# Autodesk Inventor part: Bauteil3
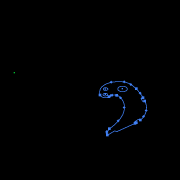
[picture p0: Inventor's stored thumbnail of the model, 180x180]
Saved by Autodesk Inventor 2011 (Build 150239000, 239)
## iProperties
Created: 2011-10
Part Number: Bauteil3
Document SubType Name: Modeling
Designer: em
Density: 1 g/cm^3
Author: em
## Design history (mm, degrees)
sketch "Skizze1"
  geometry: L1 (120.71, 20.889)-(122.705, 21.035); L2 (120.71, 20.889)-(120.347, 25.876); L3 (120.347, 25.876)-(120.71, 20.889); L4 (120.347, 25.876)-(122.342, 26.021); L5 (122.342, 26.021)-(120.347, 25.876); L6 (122.705, 21.035)-(120.71, 20.889); L7 (100.344, 48.759)-(101.309, 50.511); L8 (101.309, 50.511)-(100.344, 48.759); L9 (104.724, 46.348)-(100.344, 48.759); L10 (100.344, 48.759)-(104.724, 46.348); L11 (105.689, 48.1)-(104.724, 46.348); L12 (104.724, 46.348)-(105.689, 48.1); L13 (122.6, 19.531)-(120.219, 0); L14 (122.6, 19.531)-(120.219, 0); L15 (120.219, 0)-(118.272, 0); L16 (120.219, 0)-(118.272, 0); L17 (118.272, 0)-(118.272, -8.815); L18 (118.272, -8.815)-(118.272, 0); C1 r 4 at (80.023, 47.298); C2 r 2 at (75.666, 31.384); C3 r 2 at (70.126, 37.155); A1 r 4.511 centre (75.666, 31.384) between (73.242, 27.579) and (80.177, 31.384); 18 further points
  constraints: 36 end point, 4 centre point, 4 collinear, 4 perpendicular, 2 point on circle, 1 coincident, 32 other
